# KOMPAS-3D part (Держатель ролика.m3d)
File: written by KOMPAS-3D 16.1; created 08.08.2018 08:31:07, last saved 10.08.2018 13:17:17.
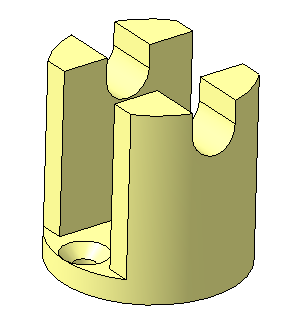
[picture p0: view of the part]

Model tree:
1. Эскиз:1
2. Операция выдавливания:1
     Расстояние 1 = 40
3. Эскиз:2
4. Вырезать элемент выдавливания:1
     Расстояние 1 = 35
5. Эскиз:3
6. Вырезать элемент выдавливания:2
     Расстояние 2 = 40; Расстояние 1 = 12
7. Эскиз:4
8. Вырезать элемент выдавливания:3
     Расстояние 2 = 35; Расстояние 1 = 5
9. Фаска:1  (labels: М0718)
     Угол = 45; Длина 1 = 2.5; Длина 2 = 2.5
